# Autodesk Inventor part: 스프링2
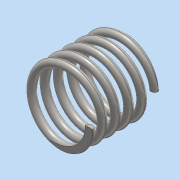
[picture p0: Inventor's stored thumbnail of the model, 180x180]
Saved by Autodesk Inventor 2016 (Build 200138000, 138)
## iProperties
Created: 2019-11
Part Number: 스프링2
Material: 스테인레스 스틸
Document SubType Name: Modeling
Designer: user
Density: 8 g/cm^3
Appearance: 반연마
Mass: 6.54853 g
Surface Area: 16.6842 cm^2
Volume: 0.818566 cm^3
Author: user
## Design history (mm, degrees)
sketch "스케치1"
  geometry: L1 (0, 0)-(8.5, 0); L2 (8.5, 0)-(8.5, -17.5); L3 (8.5, -17.5)-(0, -17.5); L4 (0, -17.5)-(0, 0); C1 r 1 at (8.5, 0)
  constraints: 8 end point, 2 parallel, 1 centre point, 1 coincident, 1 horizontal, 1 perpendicular
  dimensions: "d0" = 17 diameter of L2 L4; "d1" = 17.5 distance between parallel lines of L1 L3 (derived); "d2" = 2 diameter of C1
feature "코일1" sketch "스케치1" pitch "d3" = 10; turns "d5" = 5; dims "d4" = 17.5 (= d1), "d6" = 0, angle "d7" = 90 deg, angle "d8" = 90 deg, "d9" = 0, "d10" = 0
sketch "스케치2"
  geometry: L1 (-20, 0)-(20, 0); L2 (20, 0)-(20, -17.5); L3 (20, -17.5)-(-20, -17.5); L4 (-20, -17.5)-(-20, 0); 2 further points
  constraints: 8 end point, 2 parallel, 1 coincident, 1 horizontal, 1 midpoint, 1 perpendicular
  dimensions: "d11" = 40 distance between parallel lines of L2 L4; "d15" = 17.5 distance between parallel lines of L1 L3 (= d1)
extrude "돌출2" sketch "스케치2" stored distance "d16" = 52.5; taper "d17" = 0 deg
node "솔리드1"
